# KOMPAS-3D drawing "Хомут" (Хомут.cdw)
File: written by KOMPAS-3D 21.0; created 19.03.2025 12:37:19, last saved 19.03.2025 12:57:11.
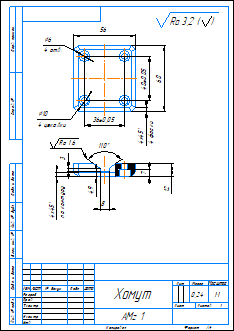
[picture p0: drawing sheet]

Sheet 1: A4, portrait

Document properties: Автор: User; Знак неуказанной шероховатости: 4; Параметр неуказанной шероховатости: Ra 3,2; Масса: 0.240541

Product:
- Part/product: Хомут
    Масса: 0.240541
    Форматы листов документа: A4

Title block, sheet 1: Наименование: Хомут; Материал: АМг 1; Масса: 0,24; Количество листов документа: 1; Форматы листов документа: A4; stored path: C:\Users\User\Desktop\Ринат все\Ринат\Перспектива\чертежи\Хомут.cdw

Views: Вид 1, Слева, Проекционный вид 3, Местный разрез 1
Referenced files in C:\Users\User\Desktop\Ринат все\Ринат\Перспектива\: Хомут.m3d
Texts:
  по контуру
  Ra 1.6
  Ra 3,2
  Ra 3,2 ( )
Dimensions and other numbers on the sheet: 60; 56; 36±0,05; 40±0,05; 4; 4 фаски; 10; 4 цековки; 6; 4 отв.; 7; 12; 8; 110; 4,9; 3; 1:1; 1; 0,24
